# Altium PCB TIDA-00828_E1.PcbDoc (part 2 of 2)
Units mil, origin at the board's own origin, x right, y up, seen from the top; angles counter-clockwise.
Board outline 3410 x 2125 mil, 4 copper layers (Top Layer, Signal Layer 1, Signal Layer 2, Bottom Layer), stack 61.6 mil thick; 60 components, 54 nets, 228 pads, 108 vias.
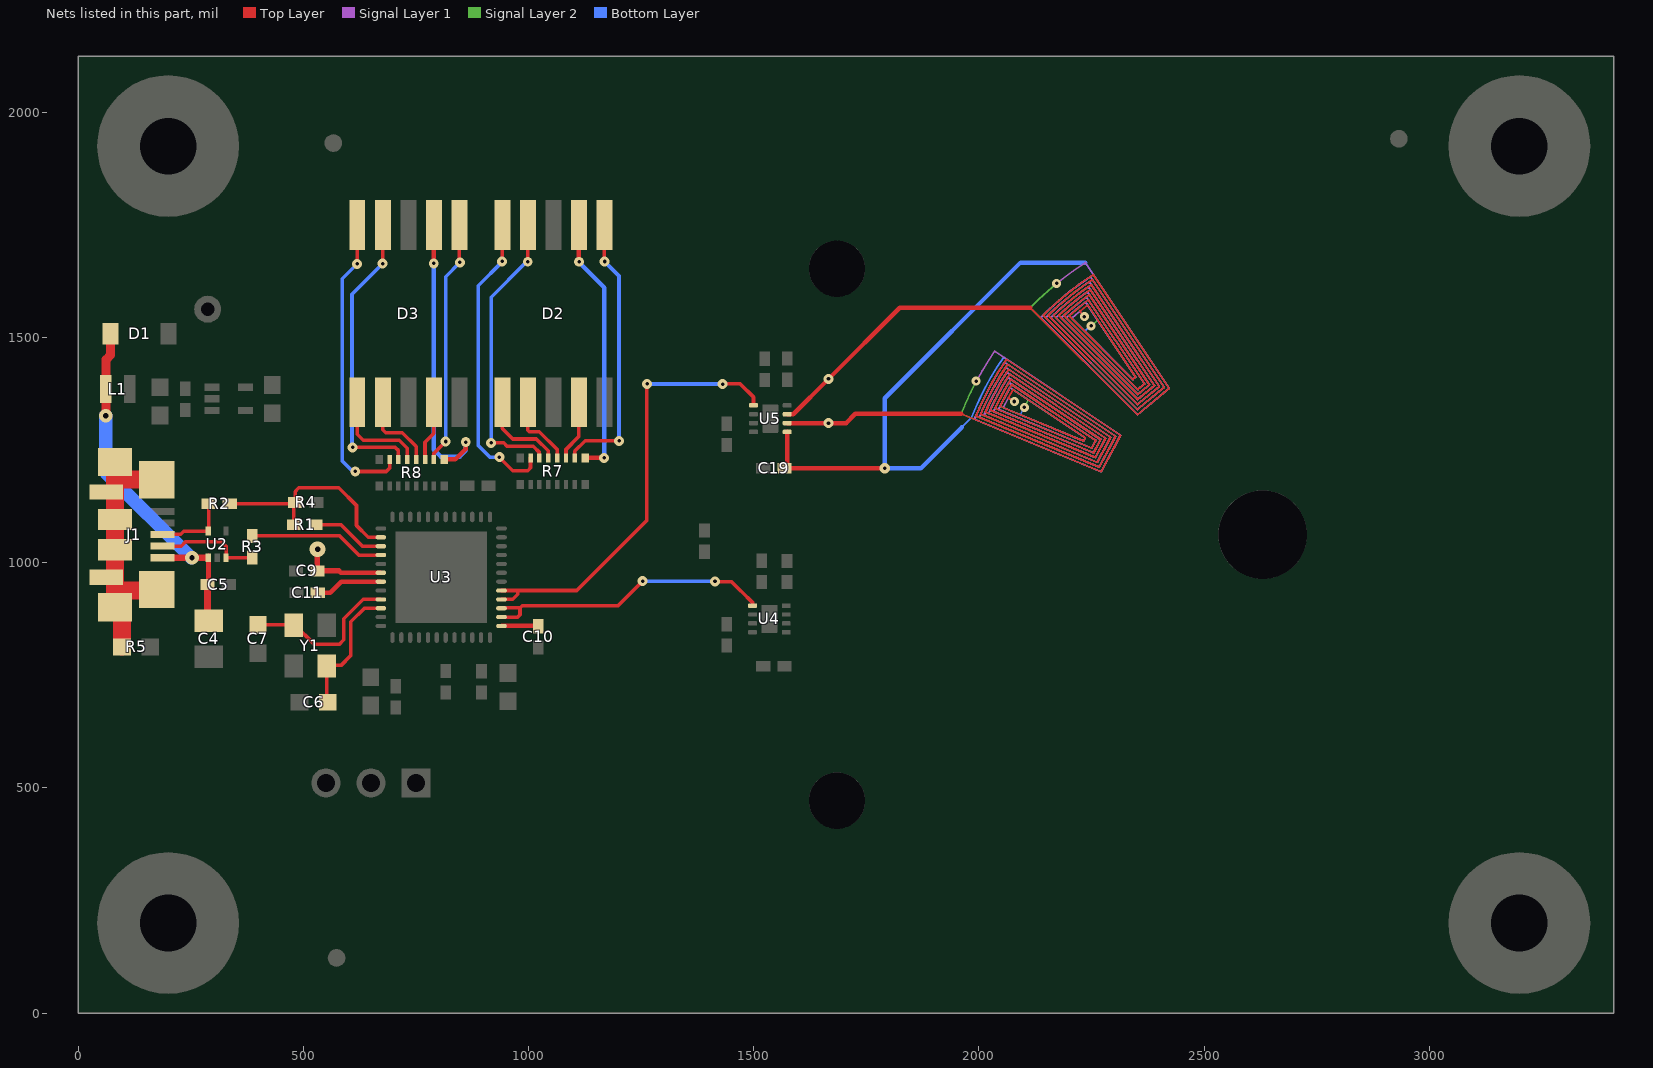
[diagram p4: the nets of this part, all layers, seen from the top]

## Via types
v1: diameter 22, hole 7.87, Top Layer to Bottom Layer, tented both sides, 64 vias
v2: diameter 19.68, hole 7.87, Top Layer to Bottom Layer, 16 vias
v3: diameter 20, hole 7.87, Top Layer to Bottom Layer, tented both sides, 12 vias
v4: diameter 22, hole 7.87, Top Layer to Bottom Layer, 9 vias
v5: diameter 30, hole 12, Top Layer to Bottom Layer, tented both sides, 2 vias
v6: diameter 24, hole 7.87, Top Layer to Bottom Layer, 2 vias
v7: diameter 35, hole 12, Top Layer to Bottom Layer, tented both sides, 1 vias
v8: diameter 50, hole 28, Top Layer to Bottom Layer, 1 vias
v9: diameter 35, hole 12, Top Layer to Bottom Layer, 1 vias

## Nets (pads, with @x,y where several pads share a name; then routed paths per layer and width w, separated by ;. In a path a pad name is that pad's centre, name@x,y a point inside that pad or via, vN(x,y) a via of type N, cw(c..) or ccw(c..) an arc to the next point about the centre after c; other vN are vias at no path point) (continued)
LC-B: C19.1 U5.1 U5.2 U5.3 | length 39389.1
  Top Layer w4: 1960.75,1330.56 2271.34,1202.29 2314.46,1282.95 2061.63,1451.81 ccw(c2630,1062.4) 1993.47,1326.06 2266.94,1212.79 2303.25,1280.73 2063.78,1440.71 ccw(c2630,1062.4) 2003.98,1330.4 2262.7,1223.24 2292.21,1278.45 2066,1429.56 ccw(c2630,1062.4) 2014.58,1334.71 2258.59,1233.62 2281.3,1276.1 2068.32,1418.37 ccw(c2630,1062.4) 2025.26,1338.95 2254.61,1243.93 2270.51,1273.68 2070.73,1407.12 ccw(c2630,1062.4) 2036.03,1343.15 2250.75,1254.17 2259.85,1271.2 2073.24,1395.84 ccw(c2630,1062.4) 2046.9,1347.3 2232.16,1270.5 cw(c2630,1062.4) 2235.97,1277.61 2075.83,1384.49 ccw(c2630,1062.4) 2065.38,1365.8 v3(2079,1358) ; 2114.31,1566.26 2352.17,1328.89 2422.88,1386.91 2253.91,1639.67 ccw(c2630,1062.4) 2142.82,1549.58 2352.12,1340.28 2411.67,1389.15 2251.65,1628.6 ccw(c2630,1062.4) 2154.19,1549.57 2352.2,1351.56 2400.6,1391.27 2249.44,1617.44 ccw(c2630,1062.4) 2165.63,1549.49 2352.38,1362.72 2389.62,1393.28 2247.3,1606.22 ccw(c2630,1062.4) 2177.12,1549.33 2352.65,1373.76 2378.73,1395.17 2245.22,1594.91 ccw(c2630,1062.4) 2188.69,1549.08 2353.01,1384.7 2367.93,1396.95 2243.22,1583.52 ccw(c2630,1062.4) 2200.31,1548.75 2342.08,1406.9 cw(c2630,1062.4) 2348.32,1412.02 2241.27,1572.05 ccw(c2630,1062.4) 2224.46,1558.78 v3(2234.06,1546.36)
  Top Layer w10: C19.1@1568.62,1211 1574.4,1216.78 U5.1@1574.4,1290.47 U5.1@1574.4,1290.72 ; C19.1@1569.62,1210 v6(1791,1210) ; U5.2@1574.4,1310.16 1666.03,1310.16 v4(1666.12,1310.07) 1705.07,1310.07 1725.56,1330.56 1960.75,1330.56 ; U5.3@1574.4,1329.84 1587.85,1329.84 v4(1666.12,1408.11) 1824.26,1566.26 2114.31,1566.26 ; U5.3@1574.4,1330.09 1588.09,1330.09
  Signal Layer 1 w4: v3@1994.43,1402.77 cw(c2630,1062.4) 2035.23,1469.89 2314.46,1282.95 2271.34,1202.29 1990.45,1318.65 cw(c2630,1062.4) 2057.14,1445.17 2303.25,1280.73 2266.94,1212.79 2000.86,1323 ; 2000.87,1323.03 cw(c2630,1062.4) 2059.36,1434.02 2292.21,1278.45 2262.7,1223.24 2011.38,1327.37 cw(c2630,1062.4) 2061.68,1422.83 2281.3,1276.1 2258.59,1233.62 2021.98,1331.66 cw(c2630,1062.4) 2064.08,1411.59 2270.51,1273.68 2254.61,1243.93 2032.66,1335.9 cw(c2630,1062.4) 2066.58,1400.3 2259.85,1271.2 2250.75,1254.17 2043.44,1340.09 cw(c2630,1062.4) 2069.16,1388.95 2235.97,1277.61 ccw(c2630,1062.4) 2232.16,1270.5 2054.31,1344.24 cw(c2630,1062.4) 2065.38,1365.8 v3(2079,1358) ; 2148.47,1543.93 2352.12,1340.28 2411.67,1389.15 2247.23,1635.26 ccw(c2630,1062.4) 2137.2,1543.89 2352.17,1328.89 2422.88,1386.91 2236.44,1666.49 ccw(c2630,1062.4) v3@2173.06,1620.09 ; 2148.5,1543.95 cw(c2630,1062.4) 2245.02,1624.11 2400.6,1391.27 2352.2,1351.56 2159.87,1543.94 cw(c2630,1062.4) 2242.87,1612.88 2389.62,1393.28 2352.38,1362.72 2171.3,1543.84 cw(c2630,1062.4) 2240.79,1601.57 ; v3(2234.06,1546.36) 2224.46,1558.78 ccw(c2630,1062.4) 2205.99,1543.09 2342,1406.98 ; 2240.79,1601.57 2378.73,1395.17 2352.65,1373.76 2182.79,1543.67 cw(c2630,1062.4) 2238.77,1590.19 2367.93,1396.95 2353.01,1384.7 2194.35,1543.42 cw(c2630,1062.4) 2236.82,1578.71 2348.32,1412.02 ccw(c2630,1062.4) 2342.08,1406.9
  Signal Layer 2 w4: v3@1994.43,1402.77 ccw(c2630,1062.4) 1960.75,1330.56 2271.34,1202.29 2314.46,1282.95 2061.63,1451.81 ccw(c2630,1062.4) 1993.47,1326.06 2266.94,1212.79 2303.25,1280.73 2063.78,1440.71 ccw(c2630,1062.4) 2003.98,1330.4 2262.7,1223.24 2292.21,1278.45 2066,1429.56 ccw(c2630,1062.4) 2014.58,1334.71 2258.59,1233.62 2281.3,1276.1 2068.32,1418.37 ccw(c2630,1062.4) 2025.26,1338.95 2254.61,1243.93 2270.51,1273.68 2070.73,1407.12 ccw(c2630,1062.4) 2036.03,1343.15 2250.75,1254.17 2259.85,1271.2 2073.24,1395.84 ccw(c2630,1062.4) 2046.9,1347.3 2232.16,1270.5 cw(c2630,1062.4) 2235.97,1277.61 ; v3@2100.78,1345.12 cw(c2630,1062.4) 2109.98,1361.69 2236,1277.54 ; v3@2173.06,1620.09 ccw(c2630,1062.4) 2114.31,1566.26 2352.17,1328.89 2422.88,1386.91 2253.91,1639.67 ccw(c2630,1062.4) 2142.82,1549.58 2352.12,1340.28 2411.67,1389.15 2251.65,1628.6 ccw(c2630,1062.4) 2154.19,1549.57 2352.2,1351.56 2400.6,1391.27 2249.44,1617.44 ccw(c2630,1062.4) 2165.63,1549.49 2352.38,1362.72 2389.62,1393.28 2247.3,1606.22 ccw(c2630,1062.4) 2177.12,1549.33 2352.65,1373.76 2378.73,1395.17 2245.22,1594.91 ccw(c2630,1062.4) 2188.69,1549.08 2353.01,1384.7 2367.93,1396.95 2243.22,1583.52 ccw(c2630,1062.4) 2200.31,1548.75 2342.08,1406.9 cw(c2630,1062.4) 2348.32,1412.02 2264.09,1537.91 ccw(c2630,1062.4) v3@2249.26,1526.12
  Bottom Layer w4: 1962.4,1301 1983.03,1321.63 cw(c2630,1062.4) 2055.03,1456.33 2314.46,1282.95 2271.34,1202.29 1990.45,1318.65 cw(c2630,1062.4) 2057.14,1445.17 2303.25,1280.73 2266.94,1212.79 2000.86,1323 ; 2000.87,1323.03 cw(c2630,1062.4) 2059.36,1434.02 2292.21,1278.45 2262.7,1223.24 2011.38,1327.37 cw(c2630,1062.4) 2061.68,1422.83 2281.3,1276.1 2258.59,1233.62 2021.98,1331.66 cw(c2630,1062.4) 2064.08,1411.59 2270.51,1273.68 2254.61,1243.93 2032.66,1335.9 cw(c2630,1062.4) 2066.58,1400.3 2259.85,1271.2 2250.75,1254.17 2043.44,1340.09 cw(c2630,1062.4) 2069.16,1388.95 2235.97,1277.61 ccw(c2630,1062.4) 2232.16,1270.5 2092.24,1328.5 cw(c2630,1062.4) v3@2100.78,1345.12 ; 2148.47,1543.93 2352.12,1340.28 2411.67,1389.15 2247.23,1635.26 ccw(c2630,1062.4) 2137.2,1543.89 2352.17,1328.89 2422.88,1386.91 2236.44,1666.49 ; 2148.5,1543.95 cw(c2630,1062.4) 2245.02,1624.11 2400.6,1391.27 2352.2,1351.56 2159.87,1543.94 cw(c2630,1062.4) 2242.87,1612.88 2389.62,1393.28 2352.38,1362.72 2171.3,1543.84 cw(c2630,1062.4) 2240.79,1601.57 ; 2240.79,1601.57 2378.73,1395.17 2352.65,1373.76 2182.79,1543.67 cw(c2630,1062.4) 2238.77,1590.19 2367.93,1396.95 2353.01,1384.7 2194.35,1543.42 cw(c2630,1062.4) 2236.82,1578.71 2348.32,1412.02 ccw(c2630,1062.4) 2342.08,1406.9 2235,1514.04 cw(c2630,1062.4) v3@2249.26,1526.12
  Bottom Layer w10: 1962.4,1301 1871.4,1210 v6(1791,1210) 1791,1365 2092.49,1666.49 2236.44,1666.49
  other v3: 2101,1345 1994,1403 2249.41,1525.93 2172.75,1620.46
MSP_DM: R3.2 U3.40 | length 303.4
  Top Layer w8: R3.2@387,1059.23 387.67,1059.9 580.65,1059.9 623.45,1017.1 U3.40@672.44,1017.1
MSP_DP: R1.1 R2.2 R4.2 U3.38 | length 481
  Top Layer w8: R2.2@337.01,1131.12 427.65,1131.12 479.25,1131.12 479.33,1131.2 R1.1@479.33,1084.39 ; R4.2@480.43,1132.3 R4.2@481.96,1133.82 481.96,1158.08 490.25,1166.38 578.92,1166.38 618.15,1127.16 618.15,1082.9 644.57,1056.47 U3.38@672.44,1056.47
MSP_PUR: R1.2 U3.39 | length 165.6
  Top Layer w8: R1.2@526.57,1084.39 583.88,1084.39 631.48,1036.79 U3.39@672.44,1036.79
MSPV18: C11.1 U3.43 | length 150.6
  Top Layer w10: C11.1@532.08,933.41 559.66,933.41 584.29,958.05 U3.43@672.44,958.05
MSPVCORE: C10.1 U3.13 | length 81.7
  Top Layer w8: C10.1@1020.81,859.62 C10.1@1021.53,858.91
  Top Layer w10: U3.13@940.16,859.62 C10.1@1020.81,859.62
NetJ1_2: J1.2 R3.1 U2.3 | length 233.8
  Top Layer w8: J1.2@187.51,1036.81 228.85,1036.81 238.64,1046.6 318.67,1046.6 329.07,1036.2 U2.3@329.07,1015.76 ; U2.3@328.5,1011.11 R3.1@391.97,1011.11
NetJ1_3: J1.3 R2.1 U2.5 | length 166.7
  Top Layer w8: J1.3@187.51,1062.4 187.51,1063.6 228.08,1063.6 234.65,1070.17 U2.5@289.13,1070.16 289.76,1070.81 R2.1@289.76,1131.12
NetJ1_6: J1.6 J1.7 J1.8 J1.9 J1.10 J1.11 J1.12 J1.13 R5.2 | length 579.4
  Top Layer w40: J1.13@82,900.98 J1.11@82,1028.94 J1.10@82,1095.86 J1.8@82,1223.82 ; 83.55,1184.45 J1.6@174.52,1184.45 ; 91.55,938.45 J1.7@182.52,938.45 ; R5.2@98,814 J1.13@98,888.68
O7SEG-A: D2.7 R7.1 | length 586.9
  Top Layer w10: D2.7@1111.99,1749.74 1111.99,1668.75 v1(1112.36,1668.39) ; R7.1@1126.17,1232.95 v1(1168.13,1232.95)
  Bottom Layer w10: v1(1112.36,1668.39) 1109.48,1665.51 1113.71,1665.51 1168.13,1611.09 v1(1168.13,1232.95)
O7SEG-A2: D3.7 R8.1 | length 672.2
  Top Layer w10: v1(789.74,1664.59) 789.99,1664.84 D3.7@789.99,1749.74 ; R8.1@813.2,1229.33 837.62,1229.33 860.74,1252.45 v1(860.74,1267.67)
  Bottom Layer w10: v1(789.74,1664.59) 789.74,1251.14 804.98,1235.9 847.17,1235.9 860.74,1249.46 v1(860.74,1267.67)
O7SEG-B: D2.6 R7.2 | length 614.9
  Top Layer w8: R7.2@1103.04,1232.95 1103.04,1247.94 1125.82,1270.72 v1(1201.08,1270.72) ; D2.6@1168.68,1749.74 1168.68,1669.03 v1(1168.9,1668.81)
  Bottom Layer w8: v1(1168.9,1668.81) 1201.08,1636.63 v1(1201.08,1270.72)
O7SEG-B2: D3.6 R8.2 | length 544.6
  Top Layer w8: R8.2@790.07,1229.33 790.07,1243.17 v1(816.1,1269.19) ; D3.6@846.68,1749.74 846.68,1667.66 v1(847.6,1666.74)
  Bottom Layer w8: v1(816.1,1269.19) 816.1,1635.24 v1(847.6,1666.74)
O7SEG-C: D2.4 R7.3 | length 135
  Top Layer w8: R7.3@1083.35,1232.95 1083.35,1251.47 1111.99,1280.11 D2.4@1111.99,1356.04
O7SEG-C2: D3.4 R8.3 | length 134.8
  Top Layer w8: R8.3@770.39,1229.33 770.39,1267.53 789.99,1287.14 D3.4@789.99,1356.04
O7SEG-D: D2.2 R7.4 | length 163.2
  Top Layer w8: D2.2@998.61,1356.04 998.61,1294.06 1001.82,1290.85 1024.26,1290.85 1063.67,1251.44 R7.4@1063.67,1232.95
O7SEG-D2: D3.2 R8.4 | length 179
  Top Layer w8: D3.2@676.61,1356.04 676.61,1295.19 683.12,1288.68 720,1288.68 750.7,1257.97 R8.4@750.7,1229.33
O7SEG-E: D2.1 R7.5 | length 196.1
  Top Layer w8: D2.1@941.91,1356.04 941.91,1298.2 965.26,1274.85 1017.63,1274.85 1043.98,1248.5 R7.5@1043.98,1232.95
O7SEG-E2: D3.1 R8.5 | length 219.6
  Top Layer w8: D3.1@619.91,1356.04 619.91,1285.19 633.06,1272.04 713.11,1272.04 731.02,1254.12 R8.5@731.02,1229.33
O7SEG-F: D2.9 R7.6 | length 651.7
  Top Layer w8: v1(917.06,1266.27) 944.82,1266.27 952.24,1258.85 1010.44,1258.85 1024.3,1245 R7.6@1024.3,1232.95 ; v1(998.42,1668.39) 998.61,1668.57 D2.9@998.61,1749.74
  Bottom Layer w8: v1(917.06,1266.27) 917.06,1589.5 993.5,1665.94 1000.87,1665.94 v1(998.42,1668.39)
O7SEG-F2: D3.9 R8.6 | length 647
  Top Layer w8: v1(609.49,1256.04) 704.38,1256.04 711.33,1249.08 R8.6@711.33,1229.33 ; v1(676.16,1664.15) 676.61,1664.6 D3.9@676.61,1749.74
  Bottom Layer w8: v1(609.49,1256.04) 608.21,1257.32 608.21,1596.21 v1(676.16,1664.15)
O7SEG-G: D2.10 R7.7 | length 675
  Top Layer w8: v1(935.47,1234.38) 965.25,1204.59 998.18,1204.59 1004.61,1211.02 R7.7@1004.61,1232.95 ; v1(941.46,1669.22) 941.91,1669.68 D2.10@941.91,1749.74
  Bottom Layer w8: v1(935.47,1234.38) 914.67,1234.38 888.69,1260.36 888.69,1614.83 941.46,1667.61 v1(941.46,1669.22)
O7SEG-G2: D3.10 R8.7 | length 674.8
  Top Layer w8: v1(615.48,1203.03) 615.79,1202.72 684.3,1202.72 691.65,1210.06 R8.7@691.65,1229.33 ; v1(619.58,1663.72) 619.91,1664.05 D3.10@619.91,1749.74
  Bottom Layer w8: v1(615.48,1203.03) 609.28,1203.03 586.49,1225.81 586.49,1630.63 v1(619.58,1663.72)
OUT-A: U3.14 U3.15 U4.5 | length 673.2
  Top Layer w8: U3.15@936.3,899.89 981.3,899.89 ; U3.14@940.16,879.31 975.72,879.31 981.3,884.89 981.3,899.89 ; v4(1253.44,959.32) 1198.78,904.67 986.08,904.67 981.3,899.89 ; v4(1414.18,958.47) 1414.68,957.97 1450.89,957.97 1472.07,936.79 1472.64,936.79 1497.6,911.83 U4.5@1497.6,904.78
  Top Layer w10: U4.5@1497.49,904.67 U4.5@1497.6,904.78
  Bottom Layer w8: v4@1254.79,957.97 v4(1253.44,959.32) 1413.33,959.32 v4(1414.18,958.47)
OUT-B: U3.16 U3.17 U5.5 | length 1008.1
  Top Layer w8: U3.16@940.16,918.68 965.09,918.68 976.3,929.89 976.3,938.36 ; U3.17@940.16,938.36 976.3,938.36 ; v4(1263.23,1396.95) 1262.25,1395.96 1262.25,1093.29 1107.32,938.36 976.3,938.36 ; v4(1431.2,1396.83) 1432.08,1397.71 1469.74,1397.71 1499.6,1367.86 U5.5@1499.6,1349.53
  Bottom Layer w8: v4@1264,1397.71 v4(1263.23,1396.95) 1431.08,1396.95 v4(1431.2,1396.83)
VBUS: C4.1 C5.1 D1.1 J1.1 L1.1 U2.1 | length 827.7
  Top Layer w10: L1.1@57.71,1389.74 L1.1@62.47,1394.5 ; U2.1@285.16,1011.22 U2.1@289.7,1015.76 ; C5.1@285.89,950.02 C5.1@285.95,949.95 ; C4.1@287.46,874.07 C4.1@290.51,871.02
  Top Layer w11: C5.1@287.46,951.59 289.13,953.26 U2.1@289.13,1011.11
  Top Layer w15: J1.1@187.51,1011.22 U2.1@285.16,1011.22 ; C4.1@287.46,874.07 C5.1@287.46,951.59
  Top Layer w20: v5(61.78,1326.21) L1.1@61.81,1385.65 ; L1.1@62.47,1394.5 62.47,1451.26 72.03,1460.81 D1.1@72.03,1510.49
  Bottom Layer w20: v5@251.53,1010.85 v5(252.99,1010.85)
  Bottom Layer w30: v5(61.78,1326.21) 61.78,1200.59 v5@251.53,1010.85
VUSB: C9.1 U3.42 | length 185.1
  Top Layer w8: v9@531.37,1024.05 v9@531.46,1024.14
  Top Layer w10: 579.17,981.82 583.26,977.73 U3.42@672.44,977.73
  Top Layer w12: v9@531.37,1024.05 C9.1@531.37,981.82 579.17,981.82
  other v9: 531.86,1030
XTAL1: C7.2 U3.45 Y1.1 | length 350.6
  Top Layer w8: C7.2@408.93,862.86 409.16,862.63 481.2,862.63 525.17,818.67 579.59,818.67 589.66,828.74 589.66,875.4 632.94,918.68 U3.45@672.44,918.68
XTAL2: C6.2 U3.46 Y1.3 | length 296.4
  Top Layer w8: Y1.3@552.01,770.75 552.01,692.83 C6.2@554.67,690.17 ; Y1.3@554.04,772.08 583.74,772.08 605.66,794 605.66,868.78 635.88,898.99 U3.46@672.44,898.99
pads on no net: D2.5 D3.5 FID1.1 FID2.1 FID3.1 H1.1 H2.1 H3.1 H4.1 H5.0 H6.0 H7.0 H8.0 J1.4 R7.8 R7.9 R8.8 R8.9 U1.4 U2.2 U3.4 U3.8 U3.9 U3.22 U3.23 U3.24 U3.25 U3.26 U3.36

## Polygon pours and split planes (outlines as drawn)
+3.3V on Signal Layer 2 "Signal Layer 2-No Net" (solid, remove dead copper, pour order 8): 25.15,18.34 1571.64,18.34 1571.64,1822.98 1570.4,1824.22 1571.64,2098.19 1296.42,2098.19 89.52,2098.19 25.26,2033.93 25.27,1823.57 25.27,1722.36 25.27,300.96 25.78,300.44
GND on Signal Layer 1 "Signal Layer 1-No Net" (solid, remove dead copper, pour order 10): 26.62,2098.68 1572.32,2098.68 1572.32,21.52 26.62,21.52
0851VDD on Top Layer "Top Layer-No Net" (solid, remove dead copper, pour order 7): 1570.87,1607.09 1332.55,1607.09 1332.16,1607.48 1289.67,1607.48 1289.38,1607.77 1286.36,1604.75 1286.36,680.86 1571.46,680.86 1571.89,681.29 1571.89,1606.46

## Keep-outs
Keep-Out Layer:
  text ".Layer_Name" at 577,-858.49 h60

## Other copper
Top Layer:
  pour cut-out: 449.53,897.59 585.52,897.59 585.74,897.8 585.95,897.59 585.95,730.25 585.52,729.82 447.59,729.82 447.59,897.11 447.99,897.51 449.41,897.51
  text ".Layer_Name" at 577,-858.49 h60
Signal Layer 1:
  pour cut-out: 582.17,897.94 584.8,895.31 584.8,730.5 446.74,730.5 448.49,732.25 448.49,897.94
  text ".Layer_Name" at 590.99,-855.67 h60
Signal Layer 2:
  pour cut-out: 576.46,896.87 584.64,888.69 584.64,731.1 449.01,731.1 448.8,731.31 448.8,896.65 450.09,896.65 450.3,896.87
  text ".Layer_Name" at 578.71,-852.61 h60
Bottom Layer:
  pour cut-out: 449.67,894.86 451.46,896.64 576.47,896.64 584.06,889.05 584.06,731.89 450.12,731.89 449.67,731.44
  text ".Layer_Name" at 577,-858.49 h60

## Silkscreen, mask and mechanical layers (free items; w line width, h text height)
Top Overlay:
  circle w10: c2630,1062.4 r688.98
  lines w8: 1990.69,1301.02 2276.17,1179.42 2280.25,1186.46 2333.67,1287.37 2070.65,1463.95 ; 1992.31,821.85 2267.34,938.21 2274.89,941.23 2326.77,847.04 2331.31,838.98 2074.4,664.67 ; 2125.82,1527.78 2353.27,1307.81 2359.13,1313.31 2442.73,1386.64 2436.86,1394.7 2269.67,1647.68 ; 2132.4,595.61 2346.56,810.74 2351.9,817.05 2437.86,749.06 2444.17,743.72 2270.32,481.97 ; 2595.17,1214.28 2624.16,1185.29 2626.14,1185.29 ; 2626.14,1279.53 2626.14,1185.29 ; 2655.14,1214.28 2626.14,1185.29 ; 2626.14,1185.29 2626.14,1185.29
  lines w10: 225,735 225.82,735.82 225.82,1275 459,1275 ; 1072.3,1155.89 1080.3,1155.89 ; 1620.42,1605.59 1286.58,1605.59 1286.58,1060.58 1286.56,1060.56 1286.56,552.21 1686,552.21 1686,1575 ; 459,1275 459,1710 326.25,1710 144.75,1710 12,1710 12,726.58 225,726.58 225,397.66 1194,397.66 1194,1275 459,1275
  text "LDC0851" at 2028.77,1991.04 h65
  text "32 Position Incremental" at 1702.62,1903.14 h50
  text "Rotary Encoder" at 1896.38,1812.58 h50
  text "USB Power" at 77.7,1652.52 h35
  text "LDC0851" at 1308.66,1556.06 h35
  text "<+5V" at 332.13,1550.24 h30
  text "LREF B" at 2381.28,1518.04 h30
  text "CHANNEL B" at 1308.36,1498.67 h35
  text "5mm dia" at 2529.93,1301.93 h30
  text "LSEN B" at 1983.65,1173.53 h30
  text "LREF A" at 1981.09,912.45 h30
  text "LDC0851" at 1308.45,623.26 h35
  text "CHANNEL A" at 1306.99,570.51 h35
  text "LSEN A" at 2378.84,570.26 h30
  text "JTAG_RST" at 822.5,513.11 h25
  text "GND" at 416.1,510.79 h25
  text "<+3.3V" at 1011.68,445.54 h30
  text "MSP430" at 240.88,416.24 h35
  text "JTAG_TEST" at 554.2,416.22 h25
  text "35mm dia" at 2530,306 h30
  text "Sensor:" at 1915.69,304.67 h30
  text "4 Layers" at 1913.34,245.08 h30
  text "7 Turns/layer" at 1912.15,179.86 h30
  text "TIDA-00828" at 1011.6,124.03 h60
  text "E1" at 1631.6,124.03 h60
  text "4 mil trace/space" at 1913.34,115.83 h30
  text ".Layer_Name" at 577,-858.49 h60
Bottom Overlay:
  circle w10: c2630,1062.4 r688.98
  lines w10: 1488.27,0 1488.27,2125 ; 1881.97,0 1881.97,2125
  text ".Layer_Name" at 577,-858.49 h60
Top Paste:
  text ".Layer_Name" at 577,-858.49 h60
Bottom Paste:
  text ".Layer_Name" at 577,-858.49 h60
Top Solder:
  text ".Layer_Name" at 577,-858.49 h60
  text ".Layer_Name" at 577,-858.49 h60
Bottom Solder:
  text ".Layer_Name" at 577,-858.49 h60
Drill Guide:
  text ".Layer_Name" at 577,-858.49 h60
M1 Board Outline:
  the board outline again, w7.01
  text ".Layer_Name" at 577,-858.49 h60
M2 Board Dimensions:
  rectangle: 0,-275 125,-150
  rectangle: 125,-400 500,-275
  lines w7: 0,-275 1000,-275 ; 125,-400 125,-150 ; 250,-400 250,-150 ; 500,-400 500,-150 ; 750,-400 750,-150 ; 0,-400 1000,-400 1000,-150 0,-150 0,-400
  text ".Layer_Name" at 577,-858.49 h60
M3 3D STEP Top:
  text ".Layer_Name" at 577,-858.49 h60
M4 3D STEP Bottom:
  text ".Layer_Name" at 577,-858.49 h60
M5 Assembly Top:
  lines w10: -292,-930.17 6308,-930.17 ; -292,-726.83 6310,-726.83 ; -292,-523.5 -292,-1133.5 3713,-1133.5 6310,-1133.5 6310,-523.5 -291.5,-523.5 -291.5,-1133.5 1284,-1133.5 ; 2173,-1133.5 2173,-523.5 ; 3440,-726.83 3440,-523.5 ; 4280,-726.83 4280,-523.5 ; 4902,-1140 4902,-937.17
  text "COMPONENTS MARKED 'DNP' SHOULD NOT BE POPULATED." at 1153.5,-318.5 h60
  text "ASSEMBLY VARIANT:" at 1153,-434 h60
  text ".VariantName" at 2189,-434 h60
  text "PCB VIEWED FROM TOP SIDE" at -228.5,-655.67 h60
  text "BOARD #:" at 2248,-655.67 h60
  text ".PRJ_Number" at 2793.5,-655.67 h60
  text "REV:" at 3638,-655.67 h60
  text ".PCB_Rev" at 3929.5,-655.67 h60
  text "SVN REV:" at 4476,-655.67 h60
  text ".VersionControl_RevNumber" at 4982,-655.67 h60
  text "TID #:" at 2248,-859 h60
  text ".TID" at 2793.5,-859 h60
  text "PLOT NAME =" at -228.5,-1064.34 h60
  text ".plot_File_Name" at 577,-1064.34 h60
  text "GENERATED    :" at 2250,-1064.34 h60
  text ".Print_Date" at 3119.5,-1064.34 h60
  text ".Print_Time" at 3848.5,-1064.34 h60
  text "TEXAS INSTRUMENTS" at 5113,-1064.34 h60
M6 Assembly Bottom:
  lines w10: -292.5,-727.33 6309.5,-727.33 ; -290.5,-930.67 6309.5,-930.67 ; 1115.5,-1140.5 1115.5,-937.67 ; 1737.5,-727.33 1737.5,-524 ; 2577.5,-727.33 2577.5,-524 ; 3844.5,-1134 3844.5,-524 ; 4733.5,-1134 6309,-1134 6309,-524 -292.5,-524 -292.5,-1134 2304.5,-1134 6309.5,-1134 6309.5,-524
  text "COMPONENTS MARKED 'DNP' SHOULD NOT BE POPULATED." at 6102,-318 h60
  text ".VariantName" at 5058,-434 h60
  text "ASSEMBLY VARIANT:" at 6097,-434 h60
  text ".VersionControl_RevNumber" at 1035.5,-656.17 h60
  text "SVN REV:" at 1541.5,-656.17 h60
  text ".PCB_Rev" at 2088,-656.17 h60
  text "REV:" at 2379.5,-656.17 h60
  text ".PRJ_Number" at 3224,-656.17 h60
  text "BOARD #:" at 3769.5,-656.17 h60
  text "PCB VIEWED FROM BOTTOM SIDE" at 6246,-656.17 h60
  text ".TID" at 3224,-859.5 h60
  text "TID #:" at 3769.5,-859.5 h60
  text "TEXAS INSTRUMENTS" at 904.5,-1064.84 h60
  text ".Print_Time" at 2169,-1064.84 h60
  text ".Print_Date" at 2898,-1064.84 h60
  text "GENERATED    :" at 3767.5,-1064.84 h60
  text ".plot_File_Name" at 5440.5,-1064.84 h60
  text "PLOT NAME =" at 6246,-1064.84 h60
M9 Title Sheet:
  drawing of 57 lines, arcs and shapes, not listed
  text "1" at 739.84,8036.5 h70
  text "2" at 3235.5,8036.5 h70
  text "3" at 5724.84,8036.5 h70
  text "4" at 8231.51,8036.5 h70
  text "5" at 10730.5,8036.5 h70
  text "6" at 13235.5,8036.5 h70
  text "A" at -416.5,6893.5 h70
  text "A" at 14383.5,6893.5 h70
  text "B" at -416.5,4513.5 h70
  text "B" at 14383.5,4513.5 h70
  text "C" at -416.5,2138.5 h70
  text "C" at 14383.5,2138.5 h70
  text "PROJECT TITLE:" at 11343.5,277.5 h45
  text ".PRJ_Title" at 11393.5,144.17 h70
  text "DESIGNED FOR:" at 11343.5,-23.5 h45
  text ".PRJ_Customer" at 11393.5,-163.5 h70
  text "D" at -416.5,-231.5 h70
  text "D" at 14383.5,-231.5 h70
  text "FILE NAME:" at 11343.5,-323.5 h45
  text ".PCB_File_Name_No_Path" at 11393.5,-443.5 h70
  text "Texas Instruments (TI) and/or its licensors do not warrant the accuracy or completeness of this specification" at 6374,-605.34 h45
  text "ENGINEER:" at 11343.5,-613.5 h45
  text "LAYOUT BY:" at 12848.5,-613.5 h45
  text "or any information contained therein. TI and/or its licensors do not warrant that this design will meet" at 6329.01,-718 h45
  text ".PRJ_Engineer" at 11393.5,-768.49 h70
  text ".PCB_Layout" at 12899,-768.49 h70
  text "the specifications, will be suitable for your application or fit for any particular purpose, or will operate in" at 6329.01,-830.67 h45
  text ".Layer_Name" at 577,-858.49 h60
  text "ALTIUM DESIGNER VERSION:" at 12848.5,-923.5 h45
  text "an implementation. TI and/or its licensors do not warrant that the design is production worthy. You should" at 6329.01,-943.33 h45
  text "completely validate and test your design implementation to confirm the system functionality for your application." at 6374,-1056 h45
  text ".print_Scale" at 11393.5,-1056.83 h70
  text ".Application_BuildNumber" at 12899,-1056.83 h70
  text "1" at 739.84,-1263.5 h70
  text "2" at 3235.5,-1263.5 h70
  text "3" at 5724.84,-1263.5 h70
  text "4" at 8231.51,-1263.5 h70
  text "5" at 10730.5,-1263.5 h70
  text "6" at 13235.5,-1263.5 h70
M10 Fab Notes:
  drawing of 189 lines, arcs and shapes, not listed
  text "NO THIEVING ALLOWED." at 9775.36,6228.33 h60
  text "DESIGN INFORMATION" at 12381.02,6028 h60
  text "MIN. TRACK WIDTH:" at 11736.46,5848 h60
  text "4" at 12832.7,5848 h60
  text "MIL" at 12987.46,5848 h60
  text "4" at 12827.8,5723.84 h60
  text "MIN. CLEARANCE:" at 11736.46,5716 h60
  text "MIL" at 12987.46,5716 h60
  text "MIN. VIA PAD SIZE:" at 11736.46,5584 h60
  text "20" at 12802.71,5584 h60
  text "MIL" at 12987.46,5584 h60
  text "0.05mm (2MIL)" at 12431.46,5442.29 h60
  text "MINIMUM ANNULAR RING" at 11407.23,5438 h60
  text "EXTERNAL" at 13139.46,5438 h60
  text "PER" at 11607.23,5320 h60
  text "IPC-D-275 CLASS 2 LEVEL C" at 11827.23,5320 h60
  text "MIL, HOLES" at 13315.46,5207.71 h60
  text "+/-" at 12923,5207 h60
  text "+/-" at 13777,5207 h60
  text "REGISTRATION TOLERANCES:" at 11407.23,5202 h60
  text "METAL" at 12607,5202 h60
  text "5" at 13183.2,5202 h60
  text "3" at 14016.2,5202 h60
  text "MIL" at 14132.46,5202 h60
  text "+/-" at 13777,5089 h60
  text "HOLE SIZE TOLERANCE (UNLESS OTHERWISE SPECIFIED):" at 11407.23,5084 h60
  text "3" at 14016.2,5084 h60
  text "MIL" at 14132.46,5084 h60
  text "MATERIAL:" at 11332.46,4874.54 h60
  text "FR-4 High Tg" at 12318.9,4734.21 h60
  text "FR-408" at 11753.46,4725.64 h60
  text "OTHER" at 13241.46,4725.64 h60
  text "X" at 12164,4722 h60
  text "62 MIL (1.6mm) +/-10%" at 12073.56,4562.92 h60
  text "THICKNESS:" at 11407.23,4558.64 h60
  text "X" at 11945.4,4558.64 h60
  text "OTHER" at 13358.46,4558.64 h60
  text "TOLERANCE:" at 11407.23,4400.64 h60
  text "X" at 12246.53,4400.64 h60
  text "ANSI IPC-6012 TYPE 3 CLASS 2" at 12433.48,4400.64 h60
  text "OTHER +/-" at 12433.46,4244.64 h60
  text "BOW & TWIST:" at 11407.23,4087.64 h60
  text "X" at 12246.53,4087.64 h60
  text "ANSI IPC-6012 TYPE 3 CLASS 2" at 12433.48,4087.64 h60
  text "OTHER +/-" at 12433.46,3929.13 h60
  text "DRILLING:" at 11332.46,3790.64 h60
  text "REFERENCE:" at 11407.23,3673.64 h60
  text "X" at 12055.46,3673.64 h60
  text "AS SHOWN" at 12242.46,3673.64 h60
  text "X" at 12956.46,3673.64 h60
  text "NC_DRILL FILES" at 13093.46,3673.64 h60
  text "PTH MIN COPPER THICKNESS:" at 11407.23,3515.64 h60
  text "X" at 12757.46,3515.64 h60
  text "1MIL" at 12894.46,3515.64 h60
  text "OTHER" at 13391.46,3515.64 h60
  text "BOARD FINISH:" at 11332.46,3356.64 h60
  text "SILKSCREEN:" at 11487.68,3238.64 h60
  text "X" at 12436.46,3238.64 h60
  text "TOP" at 12562.46,3238.64 h60
  text "X" at 12946.46,3238.64 h60
  text "BOTTOM" at 13073.46,3238.64 h60
  text "SILKSCREEN COLOR:" at 11487.68,3071.64 h60
  text "X" at 12435.42,3071.64 h60
  text "WHITE" at 12562.46,3071.64 h60
  text "OTHER" at 13073.46,3071.64 h60
  text "BLACK" at 13751.49,2920.22 h60
  text "X" at 13154.03,2916.35 h60
  text "GREEN" at 12693.46,2912.44 h60
  text "OTHER" at 13311.46,2912.44 h60
  text "SOLDER RESIST COLOR:" at 11487.68,2901.64 h60
  text "X" at 12566.42,2742.44 h60
  text "MATTE" at 12693.46,2742.44 h60
  text "SEMI-GLOSS" at 13311,2741.8 h60
  text "IMMERSION GOLD (ENIG)" at 12393.46,2553.92 h60
  text "ENEPIG" at 13731,2550.64 h60
  text "SURFACE FINISH:" at 11332.46,2549.64 h60
  text "X" at 12206.51,2549.64 h60
  text "IMM. TIN/SILVER OR EQUIV" at 11662,2392.64 h60
  text "OTHER" at 13093.46,2392.64 h60
  text "ARRAY/PANEL:" at 11332.46,2213.64 h60
  text "CUT AND TRIM PER M1 BOARD OUTLINE" at 12393.46,2209.35 h60
  text "X" at 12198.88,2059.07 h60
  text "N.C. ROUTE" at 12393.46,2057.64 h60
  text "V. SCORE" at 13259.46,2057.64 h60
  text "CERTIFICATION:" at 11332.46,1920.64 h60
  text "MATERIALS AND WORKMANSHIP FOR ALL PCBS" at 12057.46,1920.64 h60
  text "TO MEET OR EXCEED THE REQUIREMENTS OF:" at 12057.46,1822.64 h60
  text "X" at 11683.96,1686.13 h60
  text "ANSI IPC-A-600F CLASS ->" at 11822.96,1686.13 h60
  text "X" at 13462.02,1686.13 h60
  text "2" at 13580.96,1686.14 h60
  text "1" at 13265.96,1684.64 h60
  text "3" at 13934.96,1684.64 h60
  text "X" at 11686.02,1526.64 h60
  text "UL 94V-0" at 11822.96,1526.64 h60
  text "X" at 12498.02,1526.64 h60
  text "RoHS" at 12634.96,1526.64 h60
  text "OTHER" at 13279.36,1526.64 h60
  text "PER ORDER" at 13676.42,1526.64 h60
  text "ADDITIONAL REQUIREMENTS:" at 11332.46,1385.64 h60
  text "MICROSECTION:" at 11407.23,1270.64 h60
  text "YES" at 12312.96,1270.64 h60
  text "REQUIRED" at 13174.46,1114.49 h60
  text "BARE BOARD ELEC. TEST:" at 11407.23,1111.64 h60
  text "NONE" at 12712.96,1111.64 h60
  text "X" at 13047.46,1111.64 h60
  text "PER ORDER" at 13766.46,1111.64 h60
  text "MANUFACTURER'S UL:" at 11407.23,954.64 h60
  text "RAIL" at 12572.96,950.35 h60
  text "METAL" at 13064.77,950.35 h60
  text "X" at 13440,950 h60
  text "SILK" at 13576.46,950.35 h60
  text ".Layer_Name" at 577,-858.49 h60
M11 Gerber Information:
  lines w10: -292,-930.17 6308,-930.17 ; -292,-726.83 6310,-726.83 ; -292,-523.5 -292,-1133.5 3713,-1133.5 6310,-1133.5 6310,-523.5 -291.5,-523.5 -291.5,-1133.5 1284,-1133.5 ; 2173,-1133.5 2173,-523.5 ; 3440,-726.83 3440,-523.5 ; 4280,-726.83 4280,-523.5 ; 4902,-1140 4902,-937.17
  text "ALL ARTWORK VIEWED FROM TOP SIDE" at -228.5,-655.67 h60
  text "BOARD #:" at 2248,-655.67 h60
  text ".PRJ_Number" at 2793.5,-655.67 h60
  text "REV:" at 3638,-655.67 h60
  text ".PCB_Rev" at 3929.5,-655.67 h60
  text "SVN REV:" at 4476,-655.67 h60
  text ".VersionControl_RevNumber" at 4982,-655.67 h60
  text "LAYER NAME =" at -228.5,-858.49 h60
  text "TID #:" at 2248,-859 h60
  text ".TID" at 2793.5,-859 h60
  text "PLOT NAME =" at -228.5,-1064.34 h60
  text ".plot_File_Name" at 577,-1064.34 h60
  text "GENERATED    :" at 2250,-1064.34 h60
  text ".Print_Date" at 3119.5,-1064.34 h60
  text ".Print_Time" at 3848.5,-1064.34 h60
  text "TEXAS INSTRUMENTS" at 5113,-1064.34 h60
M12 Stackup:
  drawing of 295 lines, arcs and shapes, not listed
  text "Layer" at 9730.69,7710.19 h60
  text "Name" at 10140.6,7710.19 h60
  text "Material" at 11080.34,7710.19 h60
  text "Thickness" at 11940.11,7710.19 h60
  text "Constant" at 12589.94,7710.19 h60
  text "Board Layer Stack" at 13159.81,7710.19 h60
  text "1" at 9730.69,7590.19 h60
  text "Top Overlay" at 10140.6,7590.19 h60
  text "2" at 9730.69,7470.19 h60
  text "Top Solder" at 10140.6,7470.19 h60
  text "Solder Resist" at 11080.34,7470.19 h60
  text "0.40mil" at 11940.11,7470.19 h60
  text "3.5" at 12589.94,7470.19 h60
  text "3" at 9730.69,7350.19 h60
  text "Top Layer" at 10140.6,7350.19 h60
  text "Copper" at 11080.34,7350.19 h60
  text "1.40mil" at 11940.11,7350.19 h60
  text "4" at 9730.69,7230.19 h60
  text "Dielectric 1" at 10140.6,7230.19 h60
  text "FR-4" at 11080.34,7230.19 h60
  text "10.00mil" at 11940.11,7230.19 h60
  text "4.1" at 12589.94,7230.19 h60
  text "5" at 9730.69,7110.19 h60
  text "Signal Layer 1" at 10140.6,7110.19 h60
  text "Copper" at 11080.34,7110.19 h60
  text "1.40mil" at 11940.11,7110.19 h60
  text "6" at 9730.69,6990.19 h60
  text "Dielectric 2" at 10140.6,6990.19 h60
  text "FR-4" at 11080.34,6990.19 h60
  text "36.00mil" at 11940.11,6990.19 h60
  text "4.1" at 12589.94,6990.19 h60
  text "7" at 9730.69,6870.19 h60
  text "Signal Layer 2" at 10140.6,6870.19 h60
  text "Copper" at 11080.34,6870.19 h60
  text "1.40mil" at 11940.11,6870.19 h60
  text "8" at 9730.69,6750.19 h60
  text "Dielectric 3" at 10140.6,6750.19 h60
  text "FR-4" at 11080.34,6750.19 h60
  text "10.00mil" at 11940.11,6750.19 h60
  text "4.1" at 12589.94,6750.19 h60
  text "9" at 9730.69,6630.19 h60
  text "Bottom Layer" at 10140.6,6630.19 h60
  text "Copper" at 11080.34,6630.19 h60
  text "1.40mil" at 11940.11,6630.19 h60
  text "10" at 9730.69,6510.19 h60
  text "Bottom Solder" at 10140.6,6510.19 h60
  text "Solder Resist" at 11080.34,6510.19 h60
  text "0.40mil" at 11940.11,6510.19 h60
  text "3.5" at 12589.94,6510.19 h60
  text "11" at 9730.69,6390.19 h60
  text "Bottom Overlay" at 10140.6,6390.19 h60
  text ".Layer_Name" at 577,-858.49 h60
M13 Component Bodies Top:
  text ".Layer_Name" at 577,-858.49 h60
M14 Component Bodies Bottom:
  text ".Layer_Name" at 577,-858.49 h60
M15 Courtyards Top:
  text ".Layer_Name" at 577,-858.49 h60
M16 Courtyards Bottom:
  text ".Layer_Name" at 577,-858.49 h60
Drill Drawing:
  circle w1: c4984.62,2464.45 r14.93
  circle w1: c4984.62,2464.45 r24.89
  circle w1: c4984.62,2315.13 r24.89
  lines w1: 4959.74,1556.09 4972.18,1556.09 4984.62,1543.65 4997.07,1556.09 5009.51,1556.09 4997.07,1568.53 5009.51,1580.98 4997.07,1580.98 4984.62,1593.42 4972.18,1580.98 4959.74,1580.98 4972.18,1568.53 4959.74,1556.09 ; 4959.74,1742.74 5009.51,1742.74 4984.62,1692.97 4959.74,1742.74 ; 4959.74,1842.29 5009.51,1842.29 5009.51,1892.06 4959.74,1892.06 4959.74,1842.29 ; 4959.74,2004.05 4972.18,2004.05 4984.62,1991.61 4997.07,2004.05 5009.51,2004.05 4997.07,2016.49 5009.51,2028.94 4997.07,2028.94 4984.62,2041.38 4972.18,2028.94 4959.74,2028.94 4972.18,2016.49 4959.74,2004.05 ; 4959.74,2140.93 4984.62,2153.37 5009.51,2140.93 4997.07,2165.81 5009.51,2190.7 4984.62,2178.26 4959.74,2190.7 4972.18,2165.81 4959.74,2140.93 ; 4959.74,2638.66 5009.51,2638.66 4984.62,2588.89 4959.74,2638.66 ; 4969.69,1561.07 4977.16,1561.07 4984.62,1553.6 4992.09,1561.07 4999.55,1561.07 4992.09,1568.53 4999.55,1576 4992.09,1576 4984.62,1583.46 4977.16,1576 4969.69,1576 4977.16,1568.53 4969.69,1561.07 ; 4969.69,2628.7 4999.55,2628.7 4984.62,2598.84 4969.69,2628.7
  lines w12: 4891.91,1498.85 7009.93,1498.85 ; 4891.91,2693.41 7009.93,2693.41 ; 5262.27,1349.53 5262.27,2842.73 ; 5619.27,1349.53 5619.27,2842.73 ; 6280.83,1349.53 6280.83,2842.73 ; 6564.97,1349.53 6564.97,2842.73 ; 4891.91,1349.53 7009.93,1349.53 7009.93,2842.73 4891.91,2842.73 4891.91,1349.53
  text "Symbol" at 4981.5,2738.21 h72
  text "Quantity" at 5307.06,2738.21 h72
  text "Finished Hole Size" at 5664.06,2738.21 h72
  text "Plated" at 6325.63,2738.21 h72
  text "Hole Type" at 6609.77,2738.21 h72
  text "2" at 5307.06,2588.89 h60
  text "125.00mil (3.175mm)" at 5664.06,2588.89 h60
  text "NPTH" at 6325.63,2588.89 h60
  text "Round" at 6609.77,2588.89 h60
  text "1" at 5307.06,2439.57 h60
  text "197.00mil (5.004mm)" at 5664.06,2439.57 h60
  text "NPTH" at 6325.63,2439.57 h60
  text "Round" at 6609.77,2439.57 h60
  text "103" at 5307.06,2290.25 h60
  text "7.87mil (0.200mm)" at 5664.06,2290.25 h60
  text "PTH" at 6325.63,2290.25 h60
  text "Round" at 6609.77,2290.25 h60
  text "4" at 5307.06,2140.93 h60
  text "12.00mil (0.305mm)" at 5664.06,2140.93 h60
  text "PTH" at 6325.63,2140.93 h60
  text "Round" at 6609.77,2140.93 h60
  text "1" at 5307.06,1991.61 h60
  text "28.00mil (0.711mm)" at 5664.06,1991.61 h60
  text "PTH" at 6325.63,1991.61 h60
  text "Round" at 6609.77,1991.61 h60
  text "1" at 5307.06,1842.29 h60
  text "30.00mil (0.762mm)" at 5664.06,1842.29 h60
  text "PTH" at 6325.63,1842.29 h60
  text "Round" at 6609.77,1842.29 h60
  text "3" at 5307.06,1692.97 h60
  text "40.00mil (1.016mm)" at 5664.06,1692.97 h60
  text "PTH" at 6325.63,1692.97 h60
  text "Round" at 6609.77,1692.97 h60
  text "4" at 5307.06,1543.65 h60
  text "125.98mil (3.200mm)" at 5664.06,1543.65 h60
  text "PTH" at 6325.63,1543.65 h60
  text "Round" at 6609.77,1543.65 h60
  text "119 Total" at 5307.06,1394.33 h60
  text ".Layer_Name" at 577,-858.49 h60

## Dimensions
0,-400 to 1000,-400 on M2 Board Dimensions
0,0 to 3410,0 on M2 Board Dimensions
0,2125 to 0,0 on M2 Board Dimensions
